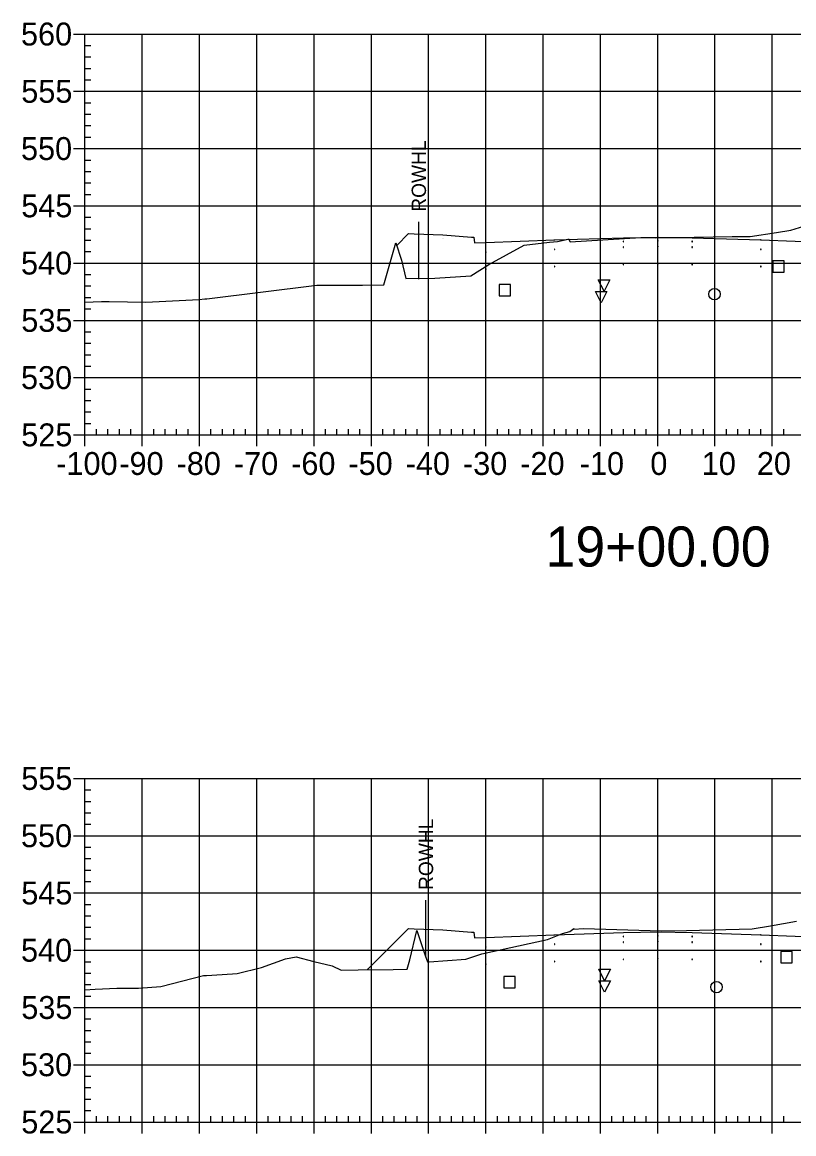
# Model space of a CAD drawing. Extents: x 708103 to 717568, y 374476 to 378707.
# Drawn here: x 708941 to 709075.7, y 377732.6 to 377926.7 of the extents above; entities that cross this region are included whole.
import ezdxf

# ---------------------------------------------------------------- set-up
doc = ezdxf.new("R2010")
doc.units = 0
for name, color, linetype in [('1', 7, 'Continuous'), ('10', 7, 'Continuous'), ('13', 7, 'Continuous'), ('14', 7, 'Continuous'), ('22', 7, 'Continuous'), ('4', 7, 'Continuous'), ('57', 7, 'Continuous'), ('Existing', 7, 'Continuous'), ('XS_Right_of_Way', 7, 'Continuous')]:
    doc.layers.add(name, color=color, linetype=linetype)

msp = doc.modelspace()

# ---------------------------------------------------------------- linework, layer by layer
for points in [[(709045.93, 377888.34), (709046.03, 377888.34), (709046.03, 377888.44), (709045.93, 377888.44)], [(709051.93, 377888.46), (709052.03, 377888.46), (709052.03, 377888.56), (709051.93, 377888.56)], [(709057.93, 377888.34), (709058.03, 377888.34), (709058.03, 377888.44), (709057.93, 377888.44)], [(709021.93, 377886.5), (709022.03, 377886.5), (709022.03, 377886.6), (709021.93, 377886.6)], [(709033.93, 377886.98), (709034.03, 377886.98), (709034.03, 377887.08), (709033.93, 377887.08)], [(709045.93, 377887.34), (709046.03, 377887.34), (709046.03, 377887.44), (709045.93, 377887.44)], [(709051.93, 377887.46), (709052.03, 377887.46), (709052.03, 377887.56), (709051.93, 377887.56)], [(709057.93, 377887.34), (709058.03, 377887.34), (709058.03, 377887.44), (709057.93, 377887.44)], [(709069.93, 377886.98), (709070.03, 377886.98), (709070.03, 377887.08), (709069.93, 377887.08)], [(709051.93, 377884.46), (709052.03, 377884.46), (709052.03, 377884.56), (709051.93, 377884.56)], [(709021.93, 377883.5), (709022.03, 377883.5), (709022.03, 377883.6), (709021.93, 377883.6)], [(709033.93, 377883.98), (709034.03, 377883.98), (709034.03, 377884.08), (709033.93, 377884.08)], [(709045.93, 377884.34), (709046.03, 377884.34), (709046.03, 377884.44), (709045.93, 377884.44)], [(709057.93, 377884.34), (709058.03, 377884.34), (709058.03, 377884.44), (709057.93, 377884.44)], [(709069.93, 377883.98), (709070.03, 377883.98), (709070.03, 377884.08), (709069.93, 377884.08)], [(709045.93, 377766.99), (709046.03, 377766.99), (709046.03, 377767.09), (709045.93, 377767.09)], [(709045.93, 377765.99), (709046.03, 377765.99), (709046.03, 377766.09), (709045.93, 377766.09)], [(709051.93, 377767.11), (709052.03, 377767.11), (709052.03, 377767.21), (709051.93, 377767.21)], [(709051.93, 377766.11), (709052.03, 377766.11), (709052.03, 377766.21), (709051.93, 377766.21)], [(709057.93, 377766.99), (709058.03, 377766.99), (709058.03, 377767.09), (709057.93, 377767.09)], [(709057.93, 377765.99), (709058.03, 377765.99), (709058.03, 377766.09), (709057.93, 377766.09)], [(709021.93, 377765.15), (709022.03, 377765.15), (709022.03, 377765.25), (709021.93, 377765.25)], [(709033.93, 377765.63), (709034.03, 377765.63), (709034.03, 377765.73), (709033.93, 377765.73)], [(709069.93, 377765.63), (709070.03, 377765.63), (709070.03, 377765.73), (709069.93, 377765.73)], [(709021.93, 377762.15), (709022.03, 377762.15), (709022.03, 377762.25), (709021.93, 377762.25)], [(709033.93, 377762.63), (709034.03, 377762.63), (709034.03, 377762.73), (709033.93, 377762.73)], [(709045.93, 377762.99), (709046.03, 377762.99), (709046.03, 377763.09), (709045.93, 377763.09)], [(709051.93, 377763.11), (709052.03, 377763.11), (709052.03, 377763.21), (709051.93, 377763.21)], [(709057.93, 377762.99), (709058.03, 377762.99), (709058.03, 377763.09), (709057.93, 377763.09)], [(709069.93, 377762.63), (709070.03, 377762.63), (709070.03, 377762.73), (709069.93, 377762.73)]]:
    msp.add_lwpolyline(points, close=True)
at = {"layer": '1'}
for points in [[(709042.61, 377879.71), (709041.61, 377881.71), (709043.61, 377881.71)], [(709042.12, 377877.68), (709041.12, 377879.68), (709043.12, 377879.68)], [(709042.71, 377759.31), (709041.71, 377761.31), (709043.71, 377761.31)], [(709042.71, 377757.31), (709041.71, 377759.31), (709043.71, 377759.31)]]:
    msp.add_lwpolyline(points, close=True, dxfattribs=at)
at = {"layer": '10'}
for points in [[(709024.3, 377878.91), (709026.3, 377878.91), (709026.3, 377880.91), (709024.3, 377880.91)], [(709025.11, 377758.07), (709027.11, 377758.07), (709027.11, 377760.07), (709025.11, 377760.07)]]:
    msp.add_lwpolyline(points, close=True, dxfattribs=at)
at = {"layer": '13'}
for centre in [(709061.9, 377879.2), (709062.25, 377758.19)]:
    msp.add_circle(centre, 1, dxfattribs=at)
at = {"layer": '14'}
for points in [[(709033.98, 377888.7), (709033.98, 377888.75), (709033.98, 377888.7), (709033.93, 377888.7), (709033.98, 377888.7), (709033.98, 377888.65), (709033.98, 377888.7), (709034.03, 377888.7)], [(709051.98, 377889.18), (709051.98, 377889.23), (709051.98, 377889.18), (709051.93, 377889.18), (709051.98, 377889.18), (709051.98, 377889.13), (709051.98, 377889.18), (709052.03, 377889.18)], [(709069.98, 377888.7), (709069.98, 377888.75), (709069.98, 377888.7), (709069.93, 377888.7), (709069.98, 377888.7), (709069.98, 377888.65), (709069.98, 377888.7), (709070.03, 377888.7)], [(709006.41, 377887.71), (709006.41, 377887.76), (709006.41, 377887.71), (709006.36, 377887.71), (709006.41, 377887.71), (709006.41, 377887.66), (709006.41, 377887.71), (709006.46, 377887.71)], [(709021.98, 377888.22), (709021.98, 377888.27), (709021.98, 377888.22), (709021.93, 377888.22), (709021.98, 377888.22), (709021.98, 377888.17), (709021.98, 377888.22), (709022.03, 377888.22)], [(709021.98, 377766.86), (709021.98, 377766.91), (709021.98, 377766.86), (709021.93, 377766.86), (709021.98, 377766.86), (709021.98, 377766.81), (709021.98, 377766.86), (709022.03, 377766.86)], [(709033.98, 377767.34), (709033.98, 377767.39), (709033.98, 377767.34), (709033.93, 377767.34), (709033.98, 377767.34), (709033.98, 377767.29), (709033.98, 377767.34), (709034.03, 377767.34)], [(709051.98, 377767.82), (709051.98, 377767.87), (709051.98, 377767.82), (709051.93, 377767.82), (709051.98, 377767.82), (709051.98, 377767.77), (709051.98, 377767.82), (709052.03, 377767.82)], [(709069.98, 377767.34), (709069.98, 377767.39), (709069.98, 377767.34), (709069.93, 377767.34), (709069.98, 377767.34), (709069.98, 377767.29), (709069.98, 377767.34), (709070.03, 377767.34)], [(709001.3, 377761.24), (709001.3, 377761.29), (709001.3, 377761.24), (709001.25, 377761.24), (709001.3, 377761.24), (709001.3, 377761.19), (709001.3, 377761.24), (709001.35, 377761.24)]]:
    msp.add_lwpolyline(points, dxfattribs=at)
at = {"layer": '22'}
for points in [[(709006.41, 377887.71), (709008.48, 377889.78), (709009.48, 377889.74), (709014.48, 377889.54), (709019.48, 377889.14), (709019.9, 377889.14), (709019.98, 377888.14), (709021.98, 377888.22), (709033.98, 377888.7), (709045.98, 377889.06), (709051.98, 377889.18), (709057.98, 377889.06), (709069.98, 377888.7), (709081.98, 377888.22), (709083.98, 377888.14), (709084.07, 377889.14), (709084.48, 377889.14), (709089.48, 377889.54), (709094.48, 377889.74), (709095.48, 377889.78), (709105.86, 377900.15)], [(709001.3, 377761.24), (709008.48, 377768.42), (709009.48, 377768.38), (709014.48, 377768.18), (709019.48, 377767.78), (709019.9, 377767.78), (709019.98, 377766.78), (709021.98, 377766.86), (709033.98, 377767.34), (709045.98, 377767.7), (709051.98, 377767.82), (709057.98, 377767.7), (709069.98, 377767.34), (709081.98, 377766.86), (709083.98, 377766.78), (709084.07, 377767.78), (709084.48, 377767.78), (709089.48, 377768.18), (709094.48, 377768.38), (709095.48, 377768.42), (709104.71, 377777.65)]]:
    msp.add_lwpolyline(points, dxfattribs=at)
at = {"layer": '4'}
for points in [[(709072.06, 377883.03), (709074.06, 377883.03), (709074.06, 377885.03), (709072.06, 377885.03)], [(709073.48, 377762.41), (709075.48, 377762.41), (709075.48, 377764.41), (709073.48, 377764.41)]]:
    msp.add_lwpolyline(points, close=True, dxfattribs=at)
at = {"layer": '57'}
for p, q in [((708949.98, 377924.63), (708951.98, 377924.63)), ((708951.98, 377924.63), (709151.98, 377924.63)), ((708951.98, 377854.63), (708951.98, 377924.63)), ((708951.98, 377854.63), (708951.98, 377924.63)), ((708961.98, 377854.63), (708961.98, 377924.63)), ((708971.98, 377854.63), (708971.98, 377924.63)), ((708981.98, 377854.63), (708981.98, 377924.63)), ((708991.98, 377854.63), (708991.98, 377924.63)), ((709001.98, 377854.63), (709001.98, 377924.63)), ((709011.98, 377854.63), (709011.98, 377924.63)), ((709021.98, 377854.63), (709021.98, 377924.63)), ((709031.98, 377854.63), (709031.98, 377924.63)), ((709041.98, 377854.63), (709041.98, 377924.63)), ((709051.98, 377854.63), (709051.98, 377924.63)), ((709061.98, 377854.63), (709061.98, 377924.63)), ((709071.98, 377854.63), (709071.98, 377924.63)), ((708951.98, 377922.63), (708952.98, 377922.63)), ((708951.98, 377920.63), (708952.98, 377920.63)), ((708951.98, 377918.63), (708952.98, 377918.63)), ((708951.98, 377916.63), (708952.98, 377916.63)), ((708949.98, 377914.63), (708951.98, 377914.63)), ((708951.98, 377914.63), (709151.98, 377914.63)), ((708951.98, 377912.63), (708952.98, 377912.63)), ((708951.98, 377910.63), (708952.98, 377910.63)), ((708951.98, 377908.63), (708952.98, 377908.63)), ((708951.98, 377906.63), (708952.98, 377906.63)), ((708949.98, 377904.63), (708951.98, 377904.63)), ((708951.98, 377904.63), (709151.98, 377904.63)), ((708951.98, 377902.63), (708952.98, 377902.63)), ((708951.98, 377900.63), (708952.98, 377900.63)), ((708951.98, 377898.63), (708952.98, 377898.63)), ((708951.98, 377896.63), (708952.98, 377896.63)), ((708949.98, 377894.63), (708951.98, 377894.63)), ((708951.98, 377894.63), (709151.98, 377894.63)), ((708951.98, 377892.63), (708952.98, 377892.63)), ((708951.98, 377890.63), (708952.98, 377890.63)), ((708951.98, 377888.63), (708952.98, 377888.63)), ((708951.98, 377886.63), (708952.98, 377886.63)), ((708949.98, 377884.63), (708951.98, 377884.63)), ((708951.98, 377884.63), (709151.98, 377884.63)), ((708951.98, 377882.63), (708952.98, 377882.63)), ((708951.98, 377880.63), (708952.98, 377880.63)), ((708951.98, 377878.63), (708952.98, 377878.63)), ((708951.98, 377876.63), (708952.98, 377876.63)), ((708949.98, 377874.63), (708951.98, 377874.63)), ((708951.98, 377874.63), (709151.98, 377874.63)), ((708951.98, 377872.63), (708952.98, 377872.63)), ((708951.98, 377870.63), (708952.98, 377870.63)), ((708951.98, 377868.63), (708952.98, 377868.63)), ((708951.98, 377866.63), (708952.98, 377866.63)), ((708949.98, 377864.63), (708951.98, 377864.63)), ((708951.98, 377864.63), (709151.98, 377864.63)), ((708951.98, 377862.63), (708952.98, 377862.63)), ((708951.98, 377860.63), (708952.98, 377860.63)), ((708951.98, 377858.63), (708952.98, 377858.63)), ((708951.98, 377856.63), (708952.98, 377856.63)), ((708953.98, 377854.63), (708953.98, 377855.63)), ((708955.98, 377854.63), (708955.98, 377855.63)), ((708957.98, 377854.63), (708957.98, 377855.63)), ((708959.98, 377854.63), (708959.98, 377855.63)), ((708963.98, 377854.63), (708963.98, 377855.63)), ((708965.98, 377854.63), (708965.98, 377855.63)), ((708967.98, 377854.63), (708967.98, 377855.63)), ((708969.98, 377854.63), (708969.98, 377855.63)), ((708973.98, 377854.63), (708973.98, 377855.63)), ((708975.98, 377854.63), (708975.98, 377855.63)), ((708977.98, 377854.63), (708977.98, 377855.63)), ((708979.98, 377854.63), (708979.98, 377855.63)), ((708983.98, 377854.63), (708983.98, 377855.63)), ((708985.98, 377854.63), (708985.98, 377855.63)), ((708987.98, 377854.63), (708987.98, 377855.63)), ((708989.98, 377854.63), (708989.98, 377855.63)), ((708993.98, 377854.63), (708993.98, 377855.63)), ((708995.98, 377854.63), (708995.98, 377855.63)), ((708997.98, 377854.63), (708997.98, 377855.63)), ((708999.98, 377854.63), (708999.98, 377855.63)), ((709003.98, 377854.63), (709003.98, 377855.63)), ((709005.98, 377854.63), (709005.98, 377855.63)), ((709007.98, 377854.63), (709007.98, 377855.63)), ((709009.98, 377854.63), (709009.98, 377855.63)), ((709013.98, 377854.63), (709013.98, 377855.63)), ((709015.98, 377854.63), (709015.98, 377855.63)), ((709017.98, 377854.63), (709017.98, 377855.63)), ((709019.98, 377854.63), (709019.98, 377855.63)), ((709023.98, 377854.63), (709023.98, 377855.63)), ((709025.98, 377854.63), (709025.98, 377855.63)), ((709027.98, 377854.63), (709027.98, 377855.63)), ((709029.98, 377854.63), (709029.98, 377855.63)), ((709033.98, 377854.63), (709033.98, 377855.63)), ((709035.98, 377854.63), (709035.98, 377855.63)), ((709037.98, 377854.63), (709037.98, 377855.63)), ((709039.98, 377854.63), (709039.98, 377855.63)), ((709043.98, 377854.63), (709043.98, 377855.63)), ((709045.98, 377854.63), (709045.98, 377855.63)), ((709047.98, 377854.63), (709047.98, 377855.63)), ((709049.98, 377854.63), (709049.98, 377855.63)), ((709053.98, 377854.63), (709053.98, 377855.63)), ((709055.98, 377854.63), (709055.98, 377855.63)), ((709057.98, 377854.63), (709057.98, 377855.63)), ((709059.98, 377854.63), (709059.98, 377855.63)), ((709063.98, 377854.63), (709063.98, 377855.63)), ((709065.98, 377854.63), (709065.98, 377855.63)), ((709067.98, 377854.63), (709067.98, 377855.63)), ((709069.98, 377854.63), (709069.98, 377855.63)), ((709073.98, 377854.63), (709073.98, 377855.63)), ((708949.98, 377854.63), (708951.98, 377854.63)), ((708951.98, 377854.63), (709151.98, 377854.63)), ((708951.98, 377854.63), (709151.98, 377854.63)), ((708951.98, 377852.63), (708951.98, 377854.63)), ((708961.98, 377852.63), (708961.98, 377854.63)), ((708971.98, 377852.63), (708971.98, 377854.63)), ((708981.98, 377852.63), (708981.98, 377854.63)), ((708991.98, 377852.63), (708991.98, 377854.63)), ((709001.98, 377852.63), (709001.98, 377854.63)), ((709011.98, 377852.63), (709011.98, 377854.63)), ((709021.98, 377852.63), (709021.98, 377854.63)), ((709031.98, 377852.63), (709031.98, 377854.63)), ((709041.98, 377852.63), (709041.98, 377854.63)), ((709051.98, 377852.63), (709051.98, 377854.63)), ((709061.98, 377852.63), (709061.98, 377854.63)), ((709071.98, 377852.63), (709071.98, 377854.63)), ((708949.98, 377794.63), (708951.98, 377794.63)), ((708951.98, 377794.63), (709151.98, 377794.63)), ((708951.98, 377734.63), (708951.98, 377794.63)), ((708951.98, 377734.63), (708951.98, 377794.63)), ((708961.98, 377734.63), (708961.98, 377794.63)), ((708971.98, 377734.63), (708971.98, 377794.63)), ((708981.98, 377734.63), (708981.98, 377794.63)), ((708991.98, 377734.63), (708991.98, 377794.63)), ((709001.98, 377734.63), (709001.98, 377794.63)), ((709011.98, 377734.63), (709011.98, 377794.63)), ((709021.98, 377734.63), (709021.98, 377794.63)), ((709031.98, 377734.63), (709031.98, 377794.63)), ((709041.98, 377734.63), (709041.98, 377794.63)), ((709051.98, 377734.63), (709051.98, 377794.63)), ((709061.98, 377734.63), (709061.98, 377794.63)), ((709071.98, 377734.63), (709071.98, 377794.63)), ((708951.98, 377792.63), (708952.98, 377792.63)), ((708951.98, 377790.63), (708952.98, 377790.63)), ((708951.98, 377788.63), (708952.98, 377788.63)), ((708951.98, 377786.63), (708952.98, 377786.63)), ((708949.98, 377784.63), (708951.98, 377784.63)), ((708951.98, 377784.63), (709151.98, 377784.63)), ((708951.98, 377782.63), (708952.98, 377782.63)), ((708951.98, 377780.63), (708952.98, 377780.63)), ((708951.98, 377778.63), (708952.98, 377778.63)), ((708951.98, 377776.63), (708952.98, 377776.63)), ((708949.98, 377774.63), (708951.98, 377774.63)), ((708951.98, 377774.63), (709151.98, 377774.63)), ((708951.98, 377772.63), (708952.98, 377772.63)), ((708951.98, 377770.63), (708952.98, 377770.63)), ((708951.98, 377768.63), (708952.98, 377768.63)), ((708951.98, 377766.63), (708952.98, 377766.63)), ((708949.98, 377764.63), (708951.98, 377764.63)), ((708951.98, 377764.63), (709151.98, 377764.63)), ((708951.98, 377762.63), (708952.98, 377762.63)), ((708951.98, 377760.63), (708952.98, 377760.63)), ((708951.98, 377758.63), (708952.98, 377758.63)), ((708951.98, 377756.63), (708952.98, 377756.63)), ((708949.98, 377754.63), (708951.98, 377754.63)), ((708951.98, 377754.63), (709151.98, 377754.63)), ((708951.98, 377752.63), (708952.98, 377752.63)), ((708951.98, 377750.63), (708952.98, 377750.63)), ((708951.98, 377748.63), (708952.98, 377748.63)), ((708951.98, 377746.63), (708952.98, 377746.63)), ((708949.98, 377744.63), (708951.98, 377744.63)), ((708951.98, 377744.63), (709151.98, 377744.63)), ((708951.98, 377742.63), (708952.98, 377742.63)), ((708951.98, 377740.63), (708952.98, 377740.63)), ((708951.98, 377738.63), (708952.98, 377738.63)), ((708951.98, 377736.63), (708952.98, 377736.63)), ((708953.98, 377734.63), (708953.98, 377735.63)), ((708955.98, 377734.63), (708955.98, 377735.63)), ((708957.98, 377734.63), (708957.98, 377735.63)), ((708959.98, 377734.63), (708959.98, 377735.63)), ((708963.98, 377734.63), (708963.98, 377735.63)), ((708965.98, 377734.63), (708965.98, 377735.63)), ((708967.98, 377734.63), (708967.98, 377735.63)), ((708969.98, 377734.63), (708969.98, 377735.63)), ((708973.98, 377734.63), (708973.98, 377735.63)), ((708975.98, 377734.63), (708975.98, 377735.63)), ((708977.98, 377734.63), (708977.98, 377735.63)), ((708979.98, 377734.63), (708979.98, 377735.63)), ((708983.98, 377734.63), (708983.98, 377735.63)), ((708985.98, 377734.63), (708985.98, 377735.63)), ((708987.98, 377734.63), (708987.98, 377735.63)), ((708989.98, 377734.63), (708989.98, 377735.63)), ((708993.98, 377734.63), (708993.98, 377735.63)), ((708995.98, 377734.63), (708995.98, 377735.63)), ((708997.98, 377734.63), (708997.98, 377735.63)), ((708999.98, 377734.63), (708999.98, 377735.63)), ((709003.98, 377734.63), (709003.98, 377735.63)), ((709005.98, 377734.63), (709005.98, 377735.63)), ((709007.98, 377734.63), (709007.98, 377735.63)), ((709009.98, 377734.63), (709009.98, 377735.63)), ((709013.98, 377734.63), (709013.98, 377735.63)), ((709015.98, 377734.63), (709015.98, 377735.63)), ((709017.98, 377734.63), (709017.98, 377735.63)), ((709019.98, 377734.63), (709019.98, 377735.63)), ((709023.98, 377734.63), (709023.98, 377735.63)), ((709025.98, 377734.63), (709025.98, 377735.63)), ((709027.98, 377734.63), (709027.98, 377735.63)), ((709029.98, 377734.63), (709029.98, 377735.63)), ((709033.98, 377734.63), (709033.98, 377735.63)), ((709035.98, 377734.63), (709035.98, 377735.63)), ((709037.98, 377734.63), (709037.98, 377735.63)), ((709039.98, 377734.63), (709039.98, 377735.63)), ((709043.98, 377734.63), (709043.98, 377735.63)), ((709045.98, 377734.63), (709045.98, 377735.63)), ((709047.98, 377734.63), (709047.98, 377735.63)), ((709049.98, 377734.63), (709049.98, 377735.63)), ((709053.98, 377734.63), (709053.98, 377735.63)), ((709055.98, 377734.63), (709055.98, 377735.63)), ((709057.98, 377734.63), (709057.98, 377735.63)), ((709059.98, 377734.63), (709059.98, 377735.63)), ((709063.98, 377734.63), (709063.98, 377735.63)), ((709065.98, 377734.63), (709065.98, 377735.63)), ((709067.98, 377734.63), (709067.98, 377735.63)), ((709069.98, 377734.63), (709069.98, 377735.63)), ((709073.98, 377734.63), (709073.98, 377735.63)), ((708949.98, 377734.63), (708951.98, 377734.63)), ((708951.98, 377734.63), (709151.98, 377734.63)), ((708951.98, 377734.63), (709151.98, 377734.63)), ((708951.98, 377732.63), (708951.98, 377734.63)), ((708961.98, 377732.63), (708961.98, 377734.63)), ((708971.98, 377732.63), (708971.98, 377734.63)), ((708981.98, 377732.63), (708981.98, 377734.63)), ((708991.98, 377732.63), (708991.98, 377734.63)), ((709001.98, 377732.63), (709001.98, 377734.63)), ((709011.98, 377732.63), (709011.98, 377734.63)), ((709021.98, 377732.63), (709021.98, 377734.63)), ((709031.98, 377732.63), (709031.98, 377734.63)), ((709041.98, 377732.63), (709041.98, 377734.63)), ((709051.98, 377732.63), (709051.98, 377734.63)), ((709061.98, 377732.63), (709061.98, 377734.63)), ((709071.98, 377732.63), (709071.98, 377734.63))]:
    msp.add_line(p, q, dxfattribs=at)
at = {"layer": 'Existing'}
for points in [[(708951.98, 377877.78), (708954.89, 377877.93), (708956.2, 377877.92), (708962.6, 377877.79), (708971.92, 377878.29), (708972.9, 377878.36), (708973.26, 377878.41), (708992.47, 377880.78), (709000.45, 377880.8), (709004.14, 377880.83), (709004.98, 377883.67), (709006.25, 377888.19), (709007.26, 377885.15), (709007.99, 377881.94), (709013.09, 377882.02), (709019.33, 377882.42), (709022.48, 377884.37), (709028.65, 377887.74), (709033.11, 377888.3), (709034.48, 377888.38), (709036.35, 377888.81), (709036.42, 377888.86), (709036.69, 377888.33), (709049.03, 377889.12), (709051.64, 377889.04), (709064.99, 377889.26), (709068.09, 377889.3), (709068.13, 377889.28), (709072.71, 377889.97), (709075.24, 377890.38), (709078.23, 377891.29)], [(708951.98, 377757.74), (708953.75, 377757.81), (708957.53, 377758.01), (708961.35, 377757.98), (708965.21, 377758.31), (708972.69, 377760.19), (708973.18, 377760.21), (708977.76, 377760.48), (708978.57, 377760.55), (708982.78, 377761.6), (708986.99, 377763.11), (708988.88, 377763.46), (708991.91, 377762.65), (708995.12, 377761.93), (708996.72, 377761.15), (708999.68, 377761.23), (709005.77, 377761.29), (709008.21, 377761.31), (709008.7, 377762.97), (709009.91, 377768.05), (709011.32, 377763.86), (709011.8, 377762.61), (709012.05, 377762.59), (709018.49, 377763.09), (709021.28, 377764.01), (709032.76, 377766.51), (709035.35, 377767.58), (709036.66, 377767.88), (709037.31, 377768.4), (709037.35, 377768.33), (709039.01, 377768.44), (709052.59, 377767.99), (709056.98, 377768.06), (709068.49, 377768.36), (709071.67, 377768.89), (709076.23, 377769.73)]]:
    msp.add_lwpolyline(points, dxfattribs=at)
at = {"layer": 'XS_Right_of_Way'}
for p, q in [((709010.2, 377891.84), (709010.2, 377881.84)), ((709011.45, 377773.4), (709011.45, 377763.4))]:
    msp.add_line(p, q, dxfattribs=at)

# ---------------------------------------------------------------- texts
at = {"layer": '1'}
msp.add_text('19+00.00', height=7, dxfattribs=at).set_placement((709032.39, 377831.63))
at = {"layer": '14'}
for p in [(709009.45, 377889.69), (709009.45, 377889.02), (709014.45, 377888.82), (709009.45, 377768.33), (709009.45, 377767.67), (709014.45, 377767.47)]:
    msp.add_text('+', height=0.1, dxfattribs=at).set_placement(p)
at = {"layer": '57'}
for s, p in [('560', (708940.81, 377922.63)), ('555', (708940.86, 377912.63)), ('550', (708940.81, 377902.63)), ('545', (708940.86, 377892.63)), ('540', (708940.81, 377882.63)), ('535', (708940.86, 377872.63)), ('530', (708940.81, 377862.63)), ('525', (708940.86, 377852.63)), ('-100', (708946.97, 377847.63)), ('-90', (708957.98, 377847.63)), ('-80', (708967.98, 377847.63)), ('-70', (708977.98, 377847.63)), ('-60', (708987.98, 377847.63)), ('-50', (708997.98, 377847.63)), ('-40', (709007.98, 377847.63)), ('-30', (709017.98, 377847.63)), ('-20', (709027.98, 377847.63)), ('-10', (709038.37, 377847.63)), ('0', (709050.69, 377847.63)), ('10', (709059.68, 377847.63)), ('20', (709069.29, 377847.63)), ('555', (708940.86, 377792.63)), ('550', (708940.81, 377782.63)), ('545', (708940.86, 377772.63)), ('540', (708940.81, 377762.63)), ('535', (708940.86, 377752.63)), ('530', (708940.81, 377742.63)), ('525', (708940.86, 377732.63))]:
    msp.add_text(s, height=4, dxfattribs=at).set_placement(p)
at = {"layer": 'XS_Right_of_Way'}
for p in [(709011.52, 377893.6), (709012.77, 377775.16)]:
    msp.add_text('ROWHL', height=2.5, rotation=90, dxfattribs=at).set_placement(p)

doc.saveas('drawing.dxf')
